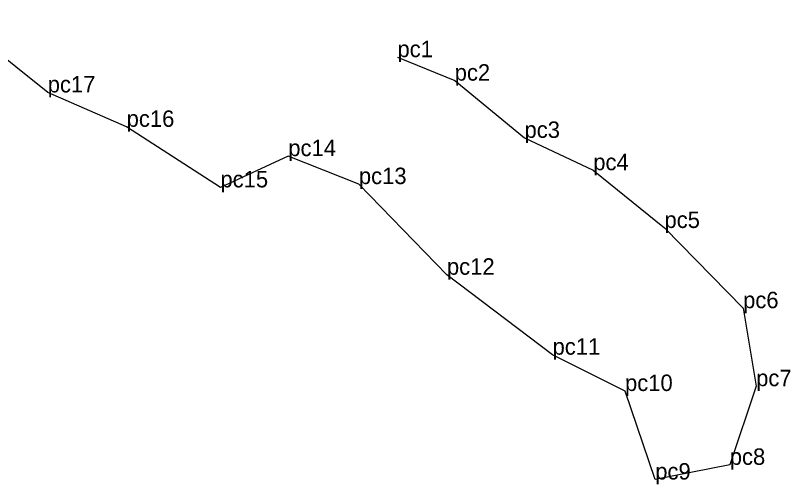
# Model space of a CAD drawing. Extents: x 2072529 to 2267990, y 436423 to 470008.
# Drawn here: x 2231388.9 to 2231671.6, y 438848.9 to 439020 of the extents above; entities that cross this region are included whole.
import ezdxf

# ---------------------------------------------------------------- set-up
doc = ezdxf.new("R2010")
doc.units = 0
doc.layers.add('Level 3', color=7, linetype='Continuous')
doc.layers.add('Old_Level_52', color=7, linetype='Continuous')

msp = doc.modelspace()

# ---------------------------------------------------------------- linework, layer by layer
at = {"layer": 'Level 3'}
for p, q in [((2231528.259, 439004.792), (2231528.259, 439004.792)), ((2231549.14, 438996.226), (2231549.14, 438996.226)), ((2231400.682, 438991.914), (2231400.682, 438991.914)), ((2231429.467, 438979.381), (2231429.467, 438979.381)), ((2231574.603, 438975.348), (2231574.603, 438975.348)), ((2231488.434, 438968.697), (2231488.434, 438968.697)), ((2231599.687, 438963.539), (2231599.687, 438963.539)), ((2231463.685, 438957.292), (2231463.685, 438957.292)), ((2231514.193, 438958.501), (2231514.193, 438958.501)), ((2231625.663, 438942.488), (2231625.663, 438942.488)), ((2231546.308, 438925.432), (2231546.308, 438925.432)), ((2231654.345, 438913.223), (2231654.345, 438913.223)), ((2231584.842, 438896.265), (2231584.842, 438896.265)), ((2231659.106, 438884.783), (2231659.106, 438884.783)), ((2231611.273, 438883.021), (2231611.273, 438883.021)), ((2231649.483, 438856.09), (2231649.483, 438856.09)), ((2231622.303, 438850.737), (2231622.303, 438850.737))]:
    msp.add_line(p, q, dxfattribs=at)
at = {"layer": 'Old_Level_52'}
msp.add_lwpolyline([(2231528.259, 439004.792), (2231549.14, 438996.226), (2231574.603, 438975.348), (2231599.687, 438963.539), (2231625.663, 438942.488), (2231654.345, 438913.223), (2231659.106, 438884.783), (2231649.483, 438856.09), (2231622.303, 438850.737), (2231611.273, 438883.021), (2231584.842, 438896.265), (2231546.308, 438925.432), (2231514.193, 438958.501), (2231488.434, 438968.697), (2231463.685, 438957.292), (2231429.467, 438979.381), (2231400.682, 438991.914), (2231365.533, 439019.989)], dxfattribs=at)

# ---------------------------------------------------------------- texts
for s, p in [('pc1', (2231528.259, 439004.792)), ('pc2', (2231549.14, 438996.226)), ('pc17', (2231400.682, 438991.914)), ('pc16', (2231429.467, 438979.381)), ('pc3', (2231574.603, 438975.348)), ('pc14', (2231488.434, 438968.697)), ('pc4', (2231599.687, 438963.539)), ('pc15', (2231463.685, 438957.292)), ('pc13', (2231514.193, 438958.501)), ('pc5', (2231625.663, 438942.488)), ('pc12', (2231546.308, 438925.432)), ('pc6', (2231654.345, 438913.223)), ('pc11', (2231584.842, 438896.265)), ('pc7', (2231659.106, 438884.783)), ('pc10', (2231611.273, 438883.021)), ('pc8', (2231649.483, 438856.09)), ('pc9', (2231622.303, 438850.737))]:
    msp.add_text(s, height=6).set_placement(p)

doc.saveas('drawing.dxf')
